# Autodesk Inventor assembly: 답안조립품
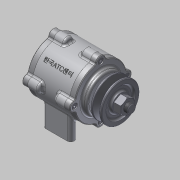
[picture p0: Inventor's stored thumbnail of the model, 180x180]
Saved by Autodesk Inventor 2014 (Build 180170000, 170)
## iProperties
Created: 2015-03
Part Number: 답안조립품
Document SubType Name: Assembly
Designer: MYHOME
Author: MYHOME
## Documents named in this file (11)
- C:\Documents and Settings\MYHOME\바탕 화면\450306V1011\답안조립품.iam
- C:\Documents and Settings\MYHOME\바탕 화면\450306V1011\본체.ipt
- C:\Documents and Settings\MYHOME\바탕 화면\450306V1011\커버2.ipt
- C:\Documents and Settings\MYHOME\바탕 화면\450306V1011\M 4 x 12.ipt
- C:\Documents and Settings\MYHOME\바탕 화면\450306V1011\커버.ipt
- C:\Documents and Settings\MYHOME\바탕 화면\450306V1011\오일실.ipt
- C:\Documents and Settings\MYHOME\바탕 화면\450306V1011\베어링 6204.ipt
- C:\Documents and Settings\MYHOME\바탕 화면\450306V1011\축.ipt
- C:\Documents and Settings\MYHOME\바탕 화면\450306V1011\키(4 x 4 x 12).ipt
- C:\Documents and Settings\MYHOME\바탕 화면\450306V1011\V벨트풀리.ipt
- C:\Documents and Settings\MYHOME\바탕 화면\450306V1011\너트 M12x1.25.ipt
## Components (14 placed, 6 different names)
1. KS B 2804 D D - 20 32 8:1 — 각도:1
2. KS B 2023 6204 - 20 x 47 x 14:1 — 각도:2
3. KS B 2023 6204 - 20 x 47 x 14:2 — 각도:3
4. KS B 1311 (I) 4 x 4 x 12:1
5. 그루브 풀리1:1
6. KS B 1012 클래스 1 일반 - 미터 M12x1.25:1 — 각도:4
7. KS B 1003 - 미터 M 4 x 12:1
8. KS B 1003 - 미터 M 4 x 12:2
9. KS B 1003 - 미터 M 4 x 12:3
10. KS B 1003 - 미터 M 4 x 12:4
11. KS B 1003 - 미터 M 4 x 12:5
12. KS B 1003 - 미터 M 4 x 12:6
13. KS B 1003 - 미터 M 4 x 12:7
14. KS B 1003 - 미터 M 4 x 12:8
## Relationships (4: Angle 4)
- 각도:1 [Angle]: KS B 2804 D D - 20 32 8:1
- 각도:2 [Angle]: KS B 2023 6204 - 20 x 47 x 14:1
- 각도:3 [Angle]: KS B 2023 6204 - 20 x 47 x 14:2
- 각도:4 [Angle]: KS B 1012 클래스 1 일반 - 미터 M12x1.25:1
